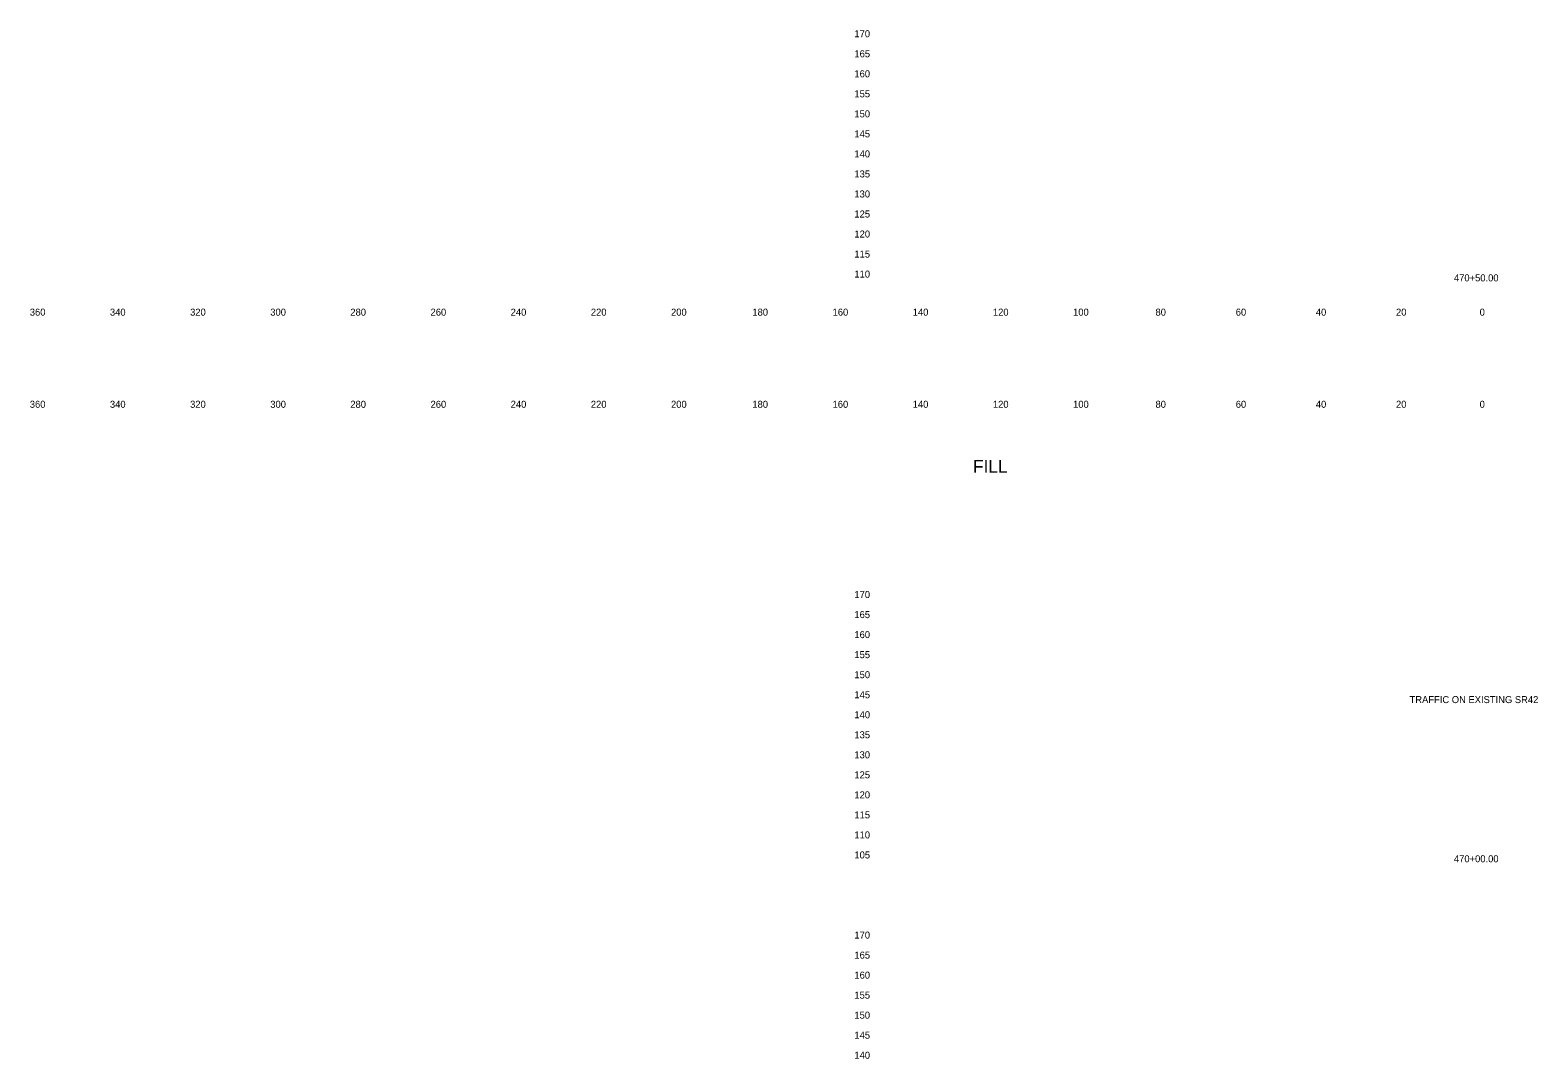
# Model space of a CAD drawing. Extents: x 21281 to 22024, y 6472 to 15198.
# Drawn here: x 21280.5 to 21656.6, y 9739.8 to 9996.6 of the extents above; entities that cross this region are included whole.
import ezdxf

# ---------------------------------------------------------------- set-up
doc = ezdxf.new("R2010")
doc.units = 0
for name, color, linetype in [('XS_SHEET_LABELS_ELEVATION', 7, 'Continuous'), ('XS_SHEET_LABELS_OFFSET', 7, 'Continuous'), ('XS_SHEET_LABELS_STATION', 7, 'Continuous')]:
    doc.layers.add(name, color=color, linetype=linetype)

msp = doc.modelspace()

# ---------------------------------------------------------------- texts
at = {"layer": 'XS_SHEET_LABELS_ELEVATION'}
for s, p in [('  170  ', (21484.84, 9994.84)), ('  165  ', (21484.84, 9989.84)), ('  160  ', (21484.84, 9984.84)), ('  155  ', (21484.84, 9979.84)), ('  150  ', (21484.84, 9974.84)), ('  145  ', (21484.84, 9969.84)), ('  140  ', (21484.84, 9964.84)), ('  135  ', (21484.84, 9959.84)), ('  130  ', (21484.84, 9954.84)), ('  125  ', (21484.84, 9949.84)), ('  120  ', (21484.84, 9944.84)), ('  115  ', (21484.84, 9939.84)), ('  110  ', (21484.84, 9934.84)), ('  170  ', (21484.84, 9854.84)), ('  165  ', (21484.84, 9849.84)), ('  160  ', (21484.84, 9844.84)), ('  155  ', (21484.84, 9839.84)), ('  150  ', (21484.84, 9834.84)), ('  145  ', (21484.84, 9829.84)), ('  140  ', (21484.84, 9824.84)), ('  135  ', (21484.84, 9819.84)), ('  130  ', (21484.84, 9814.84)), ('  125  ', (21484.84, 9809.84)), ('  120  ', (21484.84, 9804.84)), ('  115  ', (21484.84, 9799.84)), ('  110  ', (21484.84, 9794.84)), ('  105  ', (21484.84, 9789.84)), ('  170  ', (21484.84, 9769.84)), ('  165  ', (21484.84, 9764.84)), ('  160  ', (21484.84, 9759.84)), ('  155  ', (21484.84, 9754.84)), ('  150  ', (21484.84, 9749.84)), ('  145  ', (21484.84, 9744.84)), ('  140  ', (21484.84, 9739.84))]:
    msp.add_text(s, height=1.75, dxfattribs=at).set_placement(p)
at = {"layer": 'XS_SHEET_LABELS_OFFSET'}
for s, height, p in [('  360  ', 1.75, (21279.14, 9925.34)), ('  340  ', 1.75, (21299.13, 9925.34)), ('  320  ', 1.75, (21319.13, 9925.34)), ('  300  ', 1.75, (21339.13, 9925.34)), ('  280  ', 1.75, (21359.1, 9925.34)), ('  260  ', 1.75, (21379.11, 9925.34)), ('  240  ', 1.75, (21399.1, 9925.34)), ('  220  ', 1.75, (21419.1, 9925.34)), ('  200  ', 1.75, (21439.1, 9925.34)), ('  180  ', 1.75, (21459.39, 9925.34)), ('  160  ', 1.75, (21479.4, 9925.34)), ('  140  ', 1.75, (21499.39, 9925.34)), ('  120  ', 1.75, (21519.39, 9925.34)), ('  100  ', 1.75, (21539.39, 9925.34)), ('  80  ', 1.75, (21559.95, 9925.34)), ('  60  ', 1.75, (21579.97, 9925.34)), ('  40  ', 1.75, (21599.95, 9925.34)), ('  20  ', 1.75, (21619.95, 9925.34)), ('  0  ', 1.75, (21640.81, 9925.34)), ('  0  ', 1.75, (21640.81, 9925.34)), ('  360  ', 1.75, (21279.14, 9902.34)), ('  340  ', 1.75, (21299.13, 9902.34)), ('  320  ', 1.75, (21319.13, 9902.34)), ('  300  ', 1.75, (21339.13, 9902.34)), ('  280  ', 1.75, (21359.1, 9902.34)), ('  260  ', 1.75, (21379.11, 9902.34)), ('  240  ', 1.75, (21399.1, 9902.34)), ('  220  ', 1.75, (21419.1, 9902.34)), ('  200  ', 1.75, (21439.1, 9902.34)), ('  180  ', 1.75, (21459.39, 9902.34)), ('  160  ', 1.75, (21479.4, 9902.34)), ('  140  ', 1.75, (21499.39, 9902.34)), ('  120  ', 1.75, (21519.39, 9902.34)), ('  100  ', 1.75, (21539.39, 9902.34)), ('  80  ', 1.75, (21559.95, 9902.34)), ('  60  ', 1.75, (21579.97, 9902.34)), ('  40  ', 1.75, (21599.95, 9902.34)), ('  20  ', 1.75, (21619.95, 9902.34)), ('  0  ', 1.75, (21640.81, 9902.34)), ('  0  ', 1.75, (21640.81, 9902.34)), ('FILL', 3.222, (21515.74, 9886.12))]:
    msp.add_text(s, height=height, dxfattribs=at).set_placement(p)
at = {"layer": 'XS_SHEET_LABELS_STATION'}
for s, p in [('  470+50.00  ', (21634.4, 9933.89)), ('TRAFFIC ON EXISTING SR42', (21624.63, 9828.62)), ('  470+00.00  ', (21634.4, 9788.89))]:
    msp.add_text(s, height=1.75, dxfattribs=at).set_placement(p)

doc.saveas('drawing.dxf')
